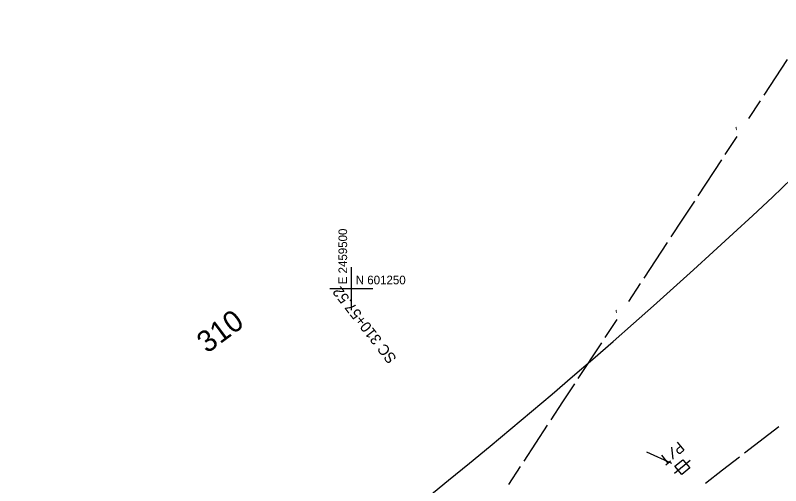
# Model space of a CAD drawing. Extents: x 2443269 to 2494951, y 591171 to 622130.
# Drawn here: x 2459344 to 2459699.3, y 601158.4 to 601377 of the extents above; entities that cross this region are included whole.
import ezdxf

# ---------------------------------------------------------------- set-up
doc = ezdxf.new("R2010")
doc.units = 0
for name, color, linetype in [('SURVEY - CENTERLINE - Preliminary', 7, 'Continuous'), ('SURVEY - CENTERLINE - Preliminary Curve Text', 7, 'Continuous'), ('SURVEY - CENTERLINE - Preliminary Text', 7, 'Continuous'), ('SURVEY - CONTROL - Grid', 7, 'Continuous'), ('SURVEY - CONTROL - Grid Text', 7, 'Continuous'), ('SURVEY - PROPERTY - ROW Lines', 7, 'Continuous'), ('SURVEY - UTILITIES - Cable (Underground) with Text', 7, 'Continuous'), ('SURVEY - UTILITIES - Electric (Overhead) with Text', 7, 'Continuous'), ('SURVEY - UTILITIES - Poles and Miscellaneous with Text', 7, 'Continuous'), ('SURVEY - UTILITIES - Telephone (Underground) with Text', 7, 'Continuous')]:
    doc.layers.add(name, color=color, linetype=linetype)

# ---------------------------------------------------------------- blocks, each defined once
blk = doc.blocks.new('xpt')
at = {"layer": 'SURVEY - UTILITIES - Cable (Underground) with Text'}
for p, q in [((-4.831, 0), (4.669, 0)), ((-2.476, 2.598), (2.314, 2.598)), ((-2.476, -2.436), (-2.476, 2.598)), ((2.314, 2.598), (2.314, 2.598)), ((2.314, 2.598), (2.314, -2.436)), ((2.314, -2.436), (-2.476, -2.436)), ((-2.476, -2.436), (-2.476, -2.436)), ((2.314, -2.436), (2.314, -2.436)), ((-5.643, -10.312), (-5.643, -5.521)), ((-5.643, -5.521), (-5.643, -5.521)), ((-5.643, -5.521), (-3.532, -5.521)), ((-3.241, -5.732), (-3.532, -5.521)), ((-3.017, -6.012), (-3.241, -5.732)), ((-3.241, -5.732), (-3.241, -5.732)), ((-2.875, -6.343), (-3.017, -6.012)), ((-3.017, -6.012), (-3.017, -6.012)), ((-3.017, -7.385), (-2.875, -7.054)), ((-2.827, -6.699), (-2.875, -6.343)), ((-2.875, -6.343), (-2.875, -6.343)), ((-2.875, -7.054), (-2.827, -6.699)), ((-2.875, -7.054), (-2.875, -7.054)), ((-2.827, -6.699), (-2.827, -6.699)), ((-2.151, -10.312), (0.933, -5.521)), ((2.395, -5.521), (5.237, -5.521)), ((3.775, -5.521), (3.775, -10.312)), ((-3.532, -7.876), (-5.643, -7.876)), ((-3.532, -7.876), (-3.241, -7.665)), ((-3.241, -7.665), (-3.017, -7.385)), ((-3.241, -7.665), (-3.241, -7.665)), ((-3.017, -7.385), (-3.017, -7.385))]:
    blk.add_line(p, q, dxfattribs=at)

msp = doc.modelspace()

# ---------------------------------------------------------------- linework, layer by layer
at = {"layer": 'SURVEY - CENTERLINE - Preliminary'}
msp.add_arc((2458230.857, 602864.005), 2291.831, 308.019561, 333.410474, dxfattribs=at)
at = {"layer": 'SURVEY - CONTROL - Grid'}
for p, q in [((2459500, 601240), (2459500, 601260)), ((2459490, 601250), (2459510, 601250))]:
    msp.add_line(p, q, dxfattribs=at)
at = {"layer": 'SURVEY - PROPERTY - ROW Lines'}
msp.add_arc((2457760.017, 603350.452), 2825, 304.10395, 336.530581, dxfattribs=at)
at = {"layer": 'SURVEY - UTILITIES - Electric (Overhead) with Text'}
for p, q in [((2459691.534, 601339.829), (2459702.452, 601356.495)), ((2459684.437, 601328.995), (2459689.896, 601337.329)), ((2459673.519, 601312.329), (2459678.978, 601320.662)), ((2459660.963, 601293.163), (2459671.881, 601309.829)), ((2459653.867, 601282.329), (2459659.326, 601290.663)), ((2459648.408, 601273.996), (2459653.867, 601282.329)), ((2459635.852, 601254.83), (2459646.77, 601271.496)), ((2459628.755, 601243.997), (2459634.214, 601252.33)), ((2459617.838, 601227.33), (2459623.296, 601235.663)), ((2459605.282, 601208.164), (2459616.2, 601224.83)), ((2459598.185, 601197.331), (2459603.644, 601205.664)), ((2459592.726, 601188.997), (2459598.185, 601197.331)), ((2459580.171, 601169.831), (2459591.089, 601186.498)), ((2459573.074, 601158.998), (2459578.533, 601167.331))]:
    msp.add_line(p, q, dxfattribs=at)
at = {"layer": 'SURVEY - UTILITIES - Poles and Miscellaneous with Text'}
for p, q in [((2459636.983, 601174.097), (2459648.61, 601168.808)), ((2459653.516, 601167.029), (2459653.516, 601167.029))]:
    msp.add_line(p, q, dxfattribs=at)
at = {"layer": 'SURVEY - UTILITIES - Telephone (Underground) with Text'}
for p, q in [((2459682.499, 601173.652), (2459698.33, 601185.874)), ((2459672.208, 601165.708), (2459680.124, 601171.819)), ((2459664.293, 601159.597), (2459672.208, 601165.708))]:
    msp.add_line(p, q, dxfattribs=at)

# ---------------------------------------------------------------- block references
at = {"layer": 'SURVEY - UTILITIES - Poles and Miscellaneous with Text', "rotation": -140.14060045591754}
msp.add_blockref('xpt', (2459653.516, 601167.029), dxfattribs=at)

# ---------------------------------------------------------------- texts
at = {"layer": 'SURVEY - CENTERLINE - Preliminary Curve Text'}
msp.add_text('SC 310+57.52', height=5, rotation=128.01956, dxfattribs=at).set_placement((2459521.249, 601217.599))
at = {"layer": 'SURVEY - CENTERLINE - Preliminary Text'}
msp.add_text('310', height=10, rotation=36.7538, dxfattribs=at).set_placement((2459433.025, 601219.591))
at = {"layer": 'SURVEY - CONTROL - Grid Text'}
msp.add_text('E 2459500', height=4, rotation=90, dxfattribs=at).set_placement((2459498, 601252))
msp.add_text('N 601250', height=4, dxfattribs=at).set_placement((2459502, 601252))
at = {"layer": 'SURVEY - UTILITIES - Electric (Overhead) with Text'}
for p in [(2459682.2, 601321.019), (2459626.519, 601236.02)]:
    msp.add_text('´', height=5, rotation=56.77174, dxfattribs=at).set_placement(p)

doc.saveas('drawing.dxf')
